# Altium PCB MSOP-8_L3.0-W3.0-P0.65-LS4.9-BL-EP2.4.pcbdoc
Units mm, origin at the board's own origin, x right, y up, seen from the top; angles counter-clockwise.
Board outline 16.01 x 18.69 mm, 2 copper layers (Top Layer, Bottom Layer), stack 0 mm thick; 1 components, 0 nets, 9 pads, 0 vias.
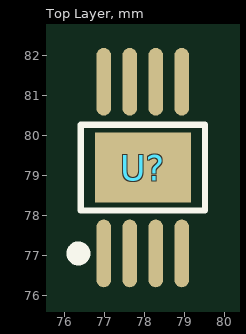
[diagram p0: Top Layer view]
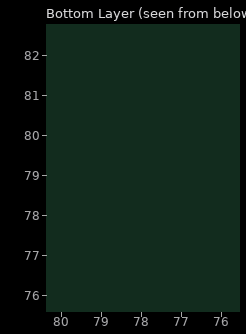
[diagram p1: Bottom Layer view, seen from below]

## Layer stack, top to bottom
Top Layer: signal copper (thickness not stored)
Bottom Layer: signal copper (thickness not stored)

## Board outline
85.861,69.85 69.85,69.85 69.85,88.542 85.861,88.542

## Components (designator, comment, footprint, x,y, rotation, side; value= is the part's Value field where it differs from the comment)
U? "" MSOP-8_L3.0-W3.0-P0.65-LS4.9-BL-EP2.4 77.959,79.2 r0 top

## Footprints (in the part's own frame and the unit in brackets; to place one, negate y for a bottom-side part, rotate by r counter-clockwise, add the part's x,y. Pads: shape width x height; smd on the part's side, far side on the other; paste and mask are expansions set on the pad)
MSOP-8_L3.0-W3.0-P0.65-LS4.9-BL-EP2.4 [mm]
  oval 0.364x1.692 smd: 1(-0.975,-2.146) 2(-0.325,-2.146) 3(0.325,-2.146) 4(0.975,-2.146) 5(0.975,2.146) 6(0.325,2.146) 7(-0.325,2.146) 8(-0.975,2.146)
  rect 2.4x1.75 smd: 9(0,0)
  silkscreen extent -1.76,-2.3 1.55,1.07

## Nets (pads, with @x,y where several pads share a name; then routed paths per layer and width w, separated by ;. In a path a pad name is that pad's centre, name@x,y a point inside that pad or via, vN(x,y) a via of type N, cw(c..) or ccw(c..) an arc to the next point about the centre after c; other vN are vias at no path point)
pads on no net: U?.1 U?.2 U?.3 U?.4 U?.5 U?.6 U?.7 U?.8 U?.9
